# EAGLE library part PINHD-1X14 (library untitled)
PIN HEADER
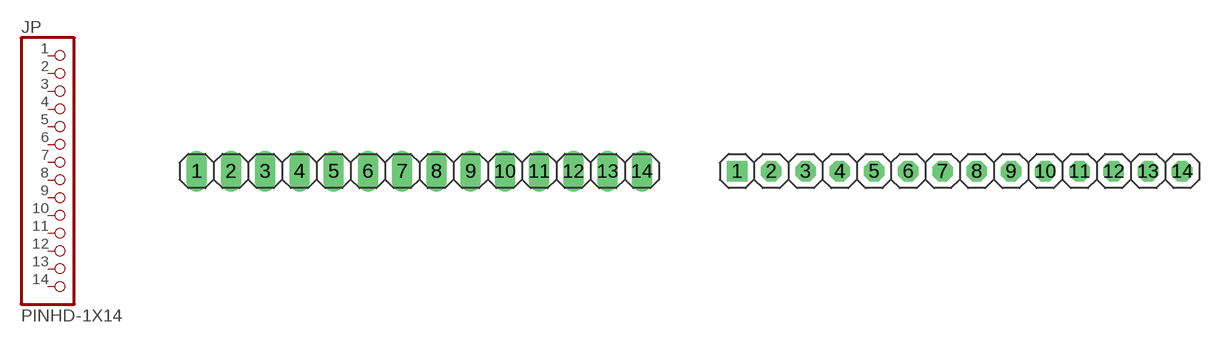
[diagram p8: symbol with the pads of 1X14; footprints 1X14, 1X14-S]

Designator prefix JP

## PINHD-1X14_2.54  [1X14]
1  1  pas
2  2  pas
3  3  pas
4  4  pas
5  5  pas
6  6  pas
7  7  pas
8  8  pas
9  9  pas
10  10  pas
11  11  pas
12  12  pas
13  13  pas
14  14  pas

## PINHD-1X14_2.54-S  [1X14-S]
Pads as for 1X14

## PINHD-1X14_2.54-90°  [1X14/90]
Pads as for 1X14

## PINHD-1X14_2.54-90°-S  [1X14/90-S]
Pads as for 1X14

## PINHD-1X14_2.00  [1X14M]
Pads as for 1X14

## PINHD-1X14_2.54-SMD  [1X14SMD]
Pads as for 1X14

## PINHD-1X14_2.54-SMD-90°  [1X14SMD/90]
Pads as for 1X14

## Footprint 1X14 (pad centres in mm)
PIN HEADER - 2.54
drill 1.016 long: 1 -16.51,0; 2 -13.97,0; 3 -11.43,0; 4 -8.89,0; 5 -6.35,0; 6 -3.81,0; 7 -1.27,0; 8 1.27,0; 9 3.81,0; 10 6.35,0; 11 8.89,0; 12 11.43,0; 13 13.97,0; 14 16.51,0

## Footprint 1X14-S (pad centres in mm)
PIN HEADER - 2.54
drill 1.016 square: 1 -16.51,0
drill 1.016 octagon: 2 -13.97,0; 3 -11.43,0; 4 -8.89,0; 5 -6.35,0; 6 -3.81,0; 7 -1.27,0; 8 1.27,0; 9 3.81,0; 10 6.35,0; 11 8.89,0; 12 11.43,0; 13 13.97,0; 14 16.51,0

## Footprint 1X14/90 (pad centres in mm)
PIN HEADER - 2.54 90°
drill 1.016 long: 1 -16.51,-3.81; 2 -13.97,-3.81; 3 -11.43,-3.81; 4 -8.89,-3.81; 5 -6.35,-3.81; 6 -3.81,-3.81; 7 -1.27,-3.81; 8 1.27,-3.81; 9 3.81,-3.81; 10 6.35,-3.81; 11 8.89,-3.81; 12 11.43,-3.81; 13 13.97,-3.81; 14 16.51,-3.81

## Footprint 1X14/90-S (pad centres in mm)
PIN HEADER - 2.54 90°
drill 1.016 square: 1 -16.51,-3.81
drill 1.016 octagon: 2 -13.97,-3.81; 3 -11.43,-3.81; 4 -8.89,-3.81; 5 -6.35,-3.81; 6 -3.81,-3.81; 7 -1.27,-3.81; 8 1.27,-3.81; 9 3.81,-3.81; 10 6.35,-3.81; 11 8.89,-3.81; 12 11.43,-3.81; 13 13.97,-3.81; 14 16.51,-3.81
